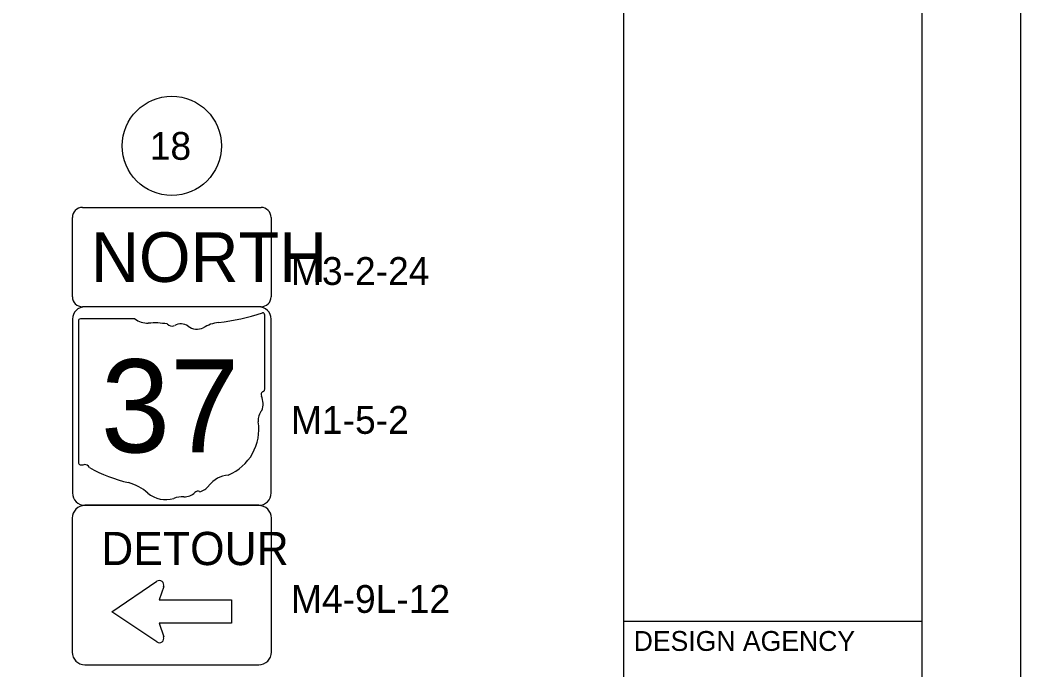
# Model space of a CAD drawing. Extents: x 0 to 680, y 0 to 440.
# Drawn here: x 579.2 to 680, y 85.1 to 150.5 of the extents above; entities that cross this region are included whole.
import ezdxf

# ---------------------------------------------------------------- set-up
doc = ezdxf.new("R2010")
doc.units = 0
for name, color, linetype in [('SH_Border', 7, 'Continuous'), ('SH_Cut_Line', 7, 'Continuous'), ('SH_Data', 7, 'Continuous'), ('SN_P_Signs', 7, 'Continuous'), ('SN_P_Text', 7, 'Continuous')]:
    doc.layers.add(name, color=color, linetype=linetype)

msp = doc.modelspace()

# ---------------------------------------------------------------- linework, layer by layer
at = {"layer": 'SH_Border'}
for p, q in [((640, 10), (640, 430)), ((640, 90), (670, 90))]:
    msp.add_line(p, q, dxfattribs=at)
msp.add_lwpolyline([(30, 430), (670, 430), (670, 10), (30, 10)], close=True, dxfattribs=at)
at = {"layer": 'SH_Cut_Line'}
msp.add_lwpolyline([(0, 0), (680, 0), (680, 440), (0, 440)], close=True, dxfattribs=at)
at = {"layer": 'SN_P_Signs'}
for p, q in [((585.49, 131.66), (603.49, 131.66)), ((584.49, 122.66), (584.49, 130.66)), ((604.49, 130.66), (604.49, 122.66)), ((603.49, 121.66), (585.49, 121.66)), ((585.1, 120.21), (585.1, 105.98)), ((590.77, 120.46), (585.28, 120.46)), ((603.85, 113.37), (603.85, 120.81)), ((603.84, 113.37), (603.85, 113.37)), ((588.46, 90.95), (592.97, 94.01)), ((593.67, 93.49), (593.23, 92.13)), ((593.23, 92.13), (600.51, 92.13)), ((600.51, 92.13), (600.51, 89.78)), ((592.97, 87.9), (588.46, 90.95)), ((600.51, 89.78), (593.23, 89.78)), ((593.23, 89.78), (593.67, 88.42))]:
    msp.add_line(p, q, dxfattribs=at)
for points in [[(603.24, 121.66), (585.74, 121.66)], [(584.49, 120.41), (584.49, 102.91)], [(604.49, 102.91), (604.49, 120.41)], [(585.74, 101.66), (603.24, 101.66)], [(603.24, 101.66), (585.74, 101.66)], [(584.45, 100.37), (584.45, 86.88)], [(604.52, 86.88), (604.52, 100.37)], [(585.74, 85.6), (603.24, 85.6)]]:
    msp.add_lwpolyline(points, dxfattribs=at)
msp.add_circle((594.49, 137.86), 5, dxfattribs=at)
for centre, radius, start, end in [((585.48, 130.66), 1, 90, 180), ((603.48, 130.66), 1, 0, 90), ((585.48, 122.66), 1, 180, 270), ((603.48, 122.66), 1, 270, 0), ((585.74, 120.41), 1.25, 90, 180), ((597.17, 139.86), 19.88, 275.8445, 288.9065), ((603.24, 120.41), 1.25, 0, 90), ((603.64, 120.84), 0.209, 351.8621, 97.738), ((585.31, 120.24), 0.217, 98.1301, 188.1301), ((592.08, 122.11), 2.11, 231.6195, 271.1119), ((592.78, 112.47), 7.56, 80.4867, 94.9883), ((599.7, 116.11), 4, 97.3462, 120.7689), ((594.49, 120.32), 0.608, 219.7921, 297.1024), ((595.39, 118.67), 1.26, 54.4667, 119.1411), ((597.02, 120.93), 1.52, 233.8562, 294.8282), ((603.8, 112.82), 0.323, 107.944, 210.337), ((603.62, 113.34), 0.223, 289.6038, 7.7341), ((601.74, 111.88), 1.94, 340.033, 23.6496), ((604.59, 110.25), 1.41, 136.8065, 186.9296), ((598.28, 109.31), 4.97, 292.3089, 8.9858), ((585.31, 105.95), 0.219, 171.9584, 258.3066), ((585.35, 107.41), 1.67, 267.339, 280.6039), ((585.69, 105.16), 0.603, 29.7484, 93.2717), ((593.3, 117.95), 14.36, 240.4129, 257.1985), ((589.02, 99.59), 4.49, 47.1842, 75.836), ((600.38, 101.99), 2.72, 94.4031, 142.5768), ((585.74, 102.91), 1.25, 180, 270), ((593.88, 105.09), 2.85, 230.7004, 286.2918), ((595.73, 104.03), 1.52, 268.777, 315.5493), ((597.11, 102.65), 0.428, 65.7517, 132.6484), ((596.93, 104.6), 1.61, 282.8732, 323.2771), ((603.24, 102.91), 1.25, 270, 0), ((595.53, 100.17), 2.34, 85.6951, 111.2099), ((585.74, 100.37), 1.28, 90, 180), ((603.24, 100.37), 1.28, 0, 90), ((593.23, 93.63), 0.459, 342.1992, 124.1969), ((593.23, 88.28), 0.459, 235.8031, 17.8008), ((585.74, 86.88), 1.28, 180, 270), ((603.24, 86.88), 1.28, 270, 0)]:
    msp.add_arc(centre, radius, start, end, dxfattribs=at)

# ---------------------------------------------------------------- texts
at = {"layer": 'SH_Data'}
msp.add_text('DESIGN AGENCY', height=2, dxfattribs=at).set_placement((641, 87))
at = {"layer": 'SN_P_Signs'}
for s, height, p in [('18', 2.8, (592.27, 136.46)), ('NORTH', 5, (586.35, 124.16)), ('37', 9.375, (587.34, 106.99)), ('DETOUR', 3.345, (587.38, 95.64))]:
    msp.add_text(s, height=height, dxfattribs=at).set_placement(p)
at = {"layer": 'SN_P_Text'}
for s, p in [('M3-2-24', (606.49, 123.86)), ('M1-5-2', (606.49, 108.86)), ('M4-9L-12', (606.49, 90.83))]:
    msp.add_text(s, height=2.8, dxfattribs=at).set_placement(p)

doc.saveas('drawing.dxf')
